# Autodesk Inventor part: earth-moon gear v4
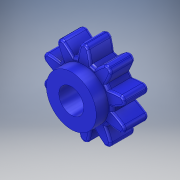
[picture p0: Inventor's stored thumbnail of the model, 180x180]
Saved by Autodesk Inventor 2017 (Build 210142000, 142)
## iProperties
Created: 2016-08
Part Number: earth-moon gear v4
Material: Generic
Document SubType Name: Modeling
Designer: Stan
Density: 1 g/cm^3
Appearance: Blue - Wall Paint - Glossy
Author: Stan
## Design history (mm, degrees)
sketch "Sketch1"
  geometry: A1 r 10.759 centre (0, 0) between (0.13, 10.758) and (-0.13, 10.758); A2 r 14.527 centre (12.708, 5.495) between (-1.082, 10.062) and (-1.722, 7.171); A3 r 14.527 centre (-12.708, 5.495) between (1.722, 7.171) and (1.082, 10.062); A4 r 10.759 centre (0, 0) between (-6.219, 8.78) and (-6.429, 8.627); A5 r 14.527 centre (7.051, 11.915) between (-6.79, 7.504) and (-5.608, 4.79); A6 r 14.527 centre (-13.511, -3.024) between (-2.822, 6.814) and (-5.039, 8.776); A7 r 10.759 centre (0, 0) between (-10.192, 3.448) and (-10.272, 3.201); A8 r 14.527 centre (-1.299, 13.785) between (-9.904, 2.08) and (-7.352, 0.579); A9 r 14.527 centre (-9.153, -10.388) between (-6.288, 3.853) and (-9.235, 4.138); A10 r 10.759 centre (0, 0) between (-10.272, -3.201) and (-10.192, -3.448); A11 r 14.527 centre (-9.153, 10.388) between (-9.235, -4.138) and (-6.288, -3.853); A12 r 14.527 centre (-1.299, -13.785) between (-7.352, -0.579) and (-9.904, -2.08); A13 r 10.759 centre (0, 0) between (-6.429, -8.627) and (-6.219, -8.78); A14 r 14.527 centre (-13.511, 3.024) between (-5.039, -8.776) and (-2.822, -6.814); A15 r 14.527 centre (7.051, -11.915) between (-5.608, -4.79) and (-6.79, -7.504); A16 r 10.759 centre (0, 0) between (-0.13, -10.758) and (0.13, -10.758); A17 r 14.527 centre (-12.708, -5.495) between (1.082, -10.062) and (1.722, -7.171); A18 r 14.527 centre (12.708, -5.495) between (-1.722, -7.171) and (-1.082, -10.062); A19 r 10.759 centre (0, 0) between (6.219, -8.78) and (6.429, -8.627); A20 r 14.527 centre (-7.051, -11.915) between (6.79, -7.504) and (5.608, -4.79); A21 r 14.527 centre (13.511, 3.024) between (2.822, -6.814) and (5.039, -8.776); A22 r 10.759 centre (0, 0) between (10.192, -3.448) and (10.272, -3.201); A23 r 14.527 centre (1.299, -13.785) between (9.904, -2.08) and (7.352, -0.579); A24 r 14.527 centre (9.153, 10.388) between (6.288, -3.853) and (9.235, -4.138); A25 r 10.759 centre (0, 0) between (10.272, 3.201) and (10.192, 3.448); A26 r 14.527 centre (9.153, -10.388) between (9.235, 4.138) and (6.288, 3.853); A27 r 14.527 centre (1.299, 13.785) between (7.352, 0.579) and (9.904, 2.08); A28 r 10.759 centre (0, 0) between (6.429, 8.627) and (6.219, 8.78); A29 r 14.527 centre (13.511, -3.024) between (5.039, 8.776) and (2.822, 6.814); A30 r 14.527 centre (-7.051, 11.915) between (5.608, 4.79) and (6.79, 7.504); A31 r 1.016 centre (-5.822, 7.813) between (-6.429, 8.627) and (-6.79, 7.504); A32 r 1.016 centre (-5.631, 7.951) between (-5.039, 8.776) and (-6.219, 8.78); A33 r 1.016 centre (-0.118, 9.743) between (-0.13, 10.758) and (-1.082, 10.062); A34 r 1.016 centre (0.118, 9.743) between (1.082, 10.062) and (0.13, 10.758); A35 r 1.016 centre (5.631, 7.951) between (6.219, 8.78) and (5.039, 8.776); A36 r 1.016 centre (5.822, 7.813) between (6.79, 7.504) and (6.429, 8.627); A37 r 1.016 centre (9.229, 3.123) between (10.192, 3.448) and (9.235, 4.138); A38 r 1.016 centre (9.302, 2.899) between (9.904, 2.08) and (10.272, 3.201); A39 r 1.016 centre (9.302, -2.899) between (10.272, -3.201) and (9.904, -2.08); A40 r 1.016 centre (9.229, -3.123) between (9.235, -4.138) and (10.192, -3.448); A41 r 1.016 centre (5.822, -7.813) between (6.429, -8.627) and (6.79, -7.504); A42 r 1.016 centre (5.631, -7.951) between (5.039, -8.776) and (6.219, -8.78); A43 r 1.016 centre (0.118, -9.743) between (0.13, -10.758) and (1.082, -10.062); A44 r 1.016 centre (-0.118, -9.743) between (-1.082, -10.062) and (-0.13, -10.758); A45 r 1.016 centre (-5.631, -7.951) between (-6.219, -8.78) and (-5.039, -8.776); A46 r 1.016 centre (-5.822, -7.813) between (-6.79, -7.504) and (-6.429, -8.627); A47 r 1.016 centre (-9.229, -3.123) between (-10.192, -3.448) and (-9.235, -4.138); A48 r 1.016 centre (-9.302, -2.899) between (-9.904, -2.08) and (-10.272, -3.201); A49 r 1.016 centre (-9.302, 2.899) between (-10.272, 3.201) and (-9.904, 2.08); A50 r 1.016 centre (-9.229, 3.123) between (-9.235, 4.138) and (-10.192, 3.448); 1 further point
  constraints: 100 point on circle, 50 centre point, 40 tangent, 19 equal radius, 8 vertical alignment, 112 other
  dimensions: "d8" = 1.016 radius of A31
extrude "Extrusion1" new body sketch "Sketch1" distance "d0" = 6.35; taper "d1" = 0 deg
fillet "Fillet1" dims "d2" = 0.508
fillet "Fillet2" dims "d3" = 0.79375
fillet "Fillet3" dims "d4" = 0.79375
sketch "Sketch2"
  geometry: C1 r 3.175 at (0, 0); C2 r 6.35 at (0, 0); 1 further point
  constraints: 2 centre point, 2 coincident
  dimensions: "d5" = 12.7 diameter of C2
extrude "Extrusion2" join sketch "Sketch2" distance "d6" = 3.175; taper "d7" = 0 deg
fillet "Fillet4" dims "d9" = 0.79375
fillet "Fillet5" dims "d10" = 0.79375
body "Solid1"
